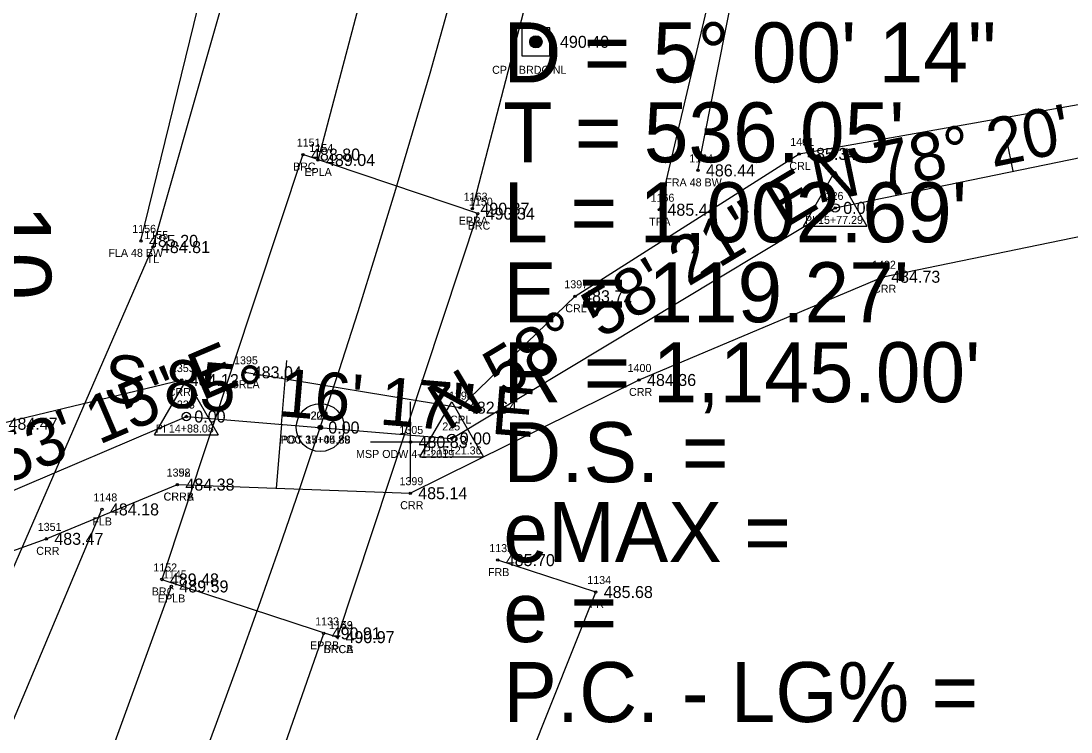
# Model space of a CAD drawing. Extents: x 1649047 to 1650429, y 896228 to 898747.
# Drawn here: x 1649848.7 to 1649979.9, y 897393.8 to 897482.7 of the extents above; entities that cross this region are included whole.
import ezdxf

# ---------------------------------------------------------------- set-up
doc = ezdxf.new("R2010")
doc.units = 0
for name, color, linetype in [('RD_EX_Bridge', 7, 'Continuous'), ('RD_EX_Bridge_txCode', 7, 'Continuous'), ('RD_EX_Fence_Other', 7, 'Continuous'), ('RD_EX_Fence_Other_txCode', 7, 'Continuous'), ('RD_EX_H2O', 7, 'Continuous'), ('RD_EX_H2O_txCode', 7, 'Continuous'), ('RD_EX_Road', 7, 'Continuous'), ('RD_EX_Road_txCode', 7, 'Continuous'), ('RD_EX_TX_Bridge_ELEV', 7, 'Continuous'), ('RD_EX_TX_Fence_Other_ELEV', 7, 'Continuous'), ('RD_EX_TX_H2O_ELEV', 7, 'Continuous'), ('RD_EX_TX_Misc_ELEV', 7, 'Continuous'), ('RD_EX_TX_Road_ELEV', 7, 'Continuous'), ('RD_EX_TX_VEG_ELEV', 7, 'Continuous'), ('RD_EX_VEG', 7, 'Continuous'), ('RD_EX_VEG_txCode', 7, 'Continuous'), ('RD_HC_Cl', 7, 'Continuous'), ('RD_HC_Data', 7, 'Continuous'), ('RD_HC_Data_Tic', 7, 'Continuous'), ('RD_HC_Survey', 7, 'Continuous'), ('RD_HC_Survey_ELEV', 7, 'Continuous'), ('RD_HC_Survey_txCode', 7, 'Continuous'), ('RD_HC_TX_Sta50', 7, 'Continuous'), ('RD_HC_txCode', 7, 'Continuous'), ('RD_SMD_Locator', 7, 'Continuous')]:
    doc.layers.add(name, color=color, linetype=linetype)

msp = doc.modelspace()

# ---------------------------------------------------------------- linework, layer by layer
at = {"layer": 'RD_EX_Bridge'}
msp.add_lwpolyline([(1649888.27, 897405.62), (1649905.8, 897458.58), (1649883.96, 897465.97), (1649866.32, 897412.83), (1649888.27, 897405.62)], dxfattribs=at)
at = {"layer": 'RD_EX_Fence_Other'}
for points in [[(1649933.32, 897463.99), (1649952.37, 897560.4), (1649962.02, 897611.35), (1649970.45, 897687.51), (1649972.87, 897702.51), (1649977.41, 897762.82), (1650017.96, 897774.28)], [(1649863.71, 897455.18), (1649880.54, 897523.95), (1649886.1, 897549.58), (1649888.54, 897562.35), (1649894.53, 897608.6), (1649889.75, 897641.9)], [(1649824.95, 897341.74), (1649840.87, 897378.89), (1649858.83, 897421.59)], [(1649933.62, 897283.21), (1649871.55, 897272.45), (1649870.07, 897285.06), (1649898.31, 897355.41), (1649920.55, 897411.26), (1649908.3, 897415.25)]]:
    msp.add_lwpolyline(points, dxfattribs=at)
at = {"layer": 'RD_EX_H2O'}
for p, q in [((1649897.4, 897425.03), (1649897.4, 897435.03)), ((1649892.4, 897430.03), (1649902.4, 897430.03))]:
    msp.add_line(p, q, dxfattribs=at)
for points in [[(1649876.68, 897438.74), (1649903.57, 897434.32), (1649917.97, 897448.25), (1649945.97, 897466.05), (1649997.07, 897475.13), (1650065.61, 897493.38), (1650098.97, 897502.84), (1650134.01, 897525.34), (1650184.58, 897534.43), (1650198.48, 897522.14), (1650246.85, 897542.98), (1650292.7, 897543.66), (1650345.21, 897558.55), (1650381.85, 897579.1), (1650386.65, 897572.92), (1650418.93, 897577.14)], [(1649868.27, 897424.7), (1649897.36, 897423.62), (1649925.96, 897437.78), (1649956.47, 897450.69), (1650000.97, 897459.86), (1650068.15, 897479.89), (1650103.08, 897490.82), (1650137.62, 897510.46), (1650180.41, 897516.6), (1650196.59, 897509.69), (1650246.91, 897526.88), (1650295.53, 897529.67), (1650347.35, 897546.47), (1650373.21, 897562.26), (1650385.6, 897559.55), (1650420.39, 897565.14)], [(1649868.8, 897437.77), (1649846.16, 897432.3), (1649822.76, 897417.33), (1649816.54, 897408.15), (1649799.76, 897408.66), (1649785.38, 897398.06), (1649752.08, 897411.48), (1649746.25, 897411.21), (1649738.94, 897415.88), (1649733.55, 897423.08), (1649741.13, 897430.63), (1649738.72, 897452.07)], [(1649610.78, 897003.58), (1649606.65, 897007.8), (1649603.49, 897018.01), (1649613.66, 897065.71), (1649613.8, 897087.62), (1649648.77, 897123.4), (1649673.15, 897145.36), (1649677.84, 897170.04), (1649704.36, 897195), (1649732.98, 897211.32), (1649741.05, 897244.13), (1649760.18, 897240.39), (1649790.48, 897304.8), (1649814.66, 897340.98), (1649827.92, 897366.62), (1649835.63, 897392.05), (1649839.2, 897413.36), (1649851.88, 897417.91), (1649868.27, 897424.7)]]:
    msp.add_lwpolyline(points, dxfattribs=at)
msp.add_circle((1649897.4, 897430.03), 0.15, dxfattribs=at)
at = {"layer": 'RD_EX_Road'}
for points in [[(1649905.13, 897459.2), (1649918.81, 897511.88), (1649930.39, 897563.05), (1649939.7, 897612.37), (1649946.83, 897662.25), (1649952.14, 897712.87), (1649954.77, 897762.63), (1649955.64, 897791.88), (1649955.33, 897812.31), (1649952.46, 897859.75), (1649947.95, 897909.71), (1649941.78, 897959.51), (1649933.15, 898009.23), (1649924.03, 898060.85), (1649913.91, 898112.48), (1649904.76, 898159.93)], [(1649885.84, 897465.29), (1649899.42, 897516.76), (1649910.69, 897567.43), (1649919.68, 897616.11), (1649926.54, 897664.67), (1649931.97, 897714.33), (1649935.04, 897763.32), (1649935.22, 897813.54), (1649932.16, 897857.76), (1649927.73, 897907.79), (1649922.24, 897954.81), (1649913.41, 898005.06), (1649903.99, 898056.19), (1649899.68, 898079.2), (1649896.48, 898096.53), (1649894.5, 898108.47), (1649884.77, 898155.82)], [(1649459.38, 896805.71), (1649486.55, 896839.62), (1649513.65, 896873.34), (1649538.22, 896902.56), (1649549.43, 896916.62), (1649583.1, 896957.27), (1649614.8, 896995.02), (1649647.06, 897035.69), (1649677.62, 897074.51), (1649708.33, 897114.44), (1649735.5, 897151.61), (1649762.11, 897192.19), (1649788.21, 897235.29), (1649812.17, 897279.73), (1649834.32, 897326.54), (1649852.94, 897371.82), (1649867.51, 897411.96)], [(1649474.75, 896792.65), (1649502.78, 896827.35), (1649565.2, 896903.92), (1649598.28, 896943.71), (1649629.8, 896982.26), (1649667.92, 897029.33), (1649693.13, 897061.44), (1649723.58, 897101.84), (1649752.37, 897141.09), (1649779.72, 897182.3), (1649806.12, 897225.84), (1649830.13, 897270.79), (1649852.39, 897317.43), (1649871.98, 897364.35), (1649886.55, 897406.09)]]:
    msp.add_lwpolyline(points, dxfattribs=at)
at = {"layer": 'RD_EX_VEG'}
for points in [[(1649617.18, 897070.52), (1649712.19, 897191.88), (1649745.96, 897241.38), (1649814.66, 897340.98), (1649833.89, 897382.46), (1649865.2, 897454.4), (1649884.45, 897522.02), (1649904.5, 897665.19), (1649923.9, 897762.32), (1649882.75, 898072.18)], [(1649928.51, 897459.07), (1649952.37, 897560.4), (1649962.02, 897611.35), (1649970.45, 897687.51), (1649977.41, 897762.82)]]:
    msp.add_lwpolyline(points, dxfattribs=at)
at = {"layer": 'RD_HC_Cl'}
for p, q in [((1649950.48, 897459.3), (1650001.12, 897469.74)), ((1649902.55, 897430.47), (1649950.48, 897459.3)), ((1649835.25, 897418.65), (1649869.38, 897433.21)), ((1649869.38, 897433.21), (1649902.55, 897430.47))]:
    msp.add_line(p, q, dxfattribs=at)
msp.add_arc((1648799.37, 897792.37), 1145, 320.82481, 10.99954, dxfattribs=at)
at = {"layer": 'RD_HC_Data'}
for p, q in [((1649946.51, 897457.01), (1649950.48, 897463.88)), ((1649950.48, 897463.88), (1649954.45, 897457.01)), ((1649946.51, 897457.01), (1649954.45, 897457.01)), ((1649865.41, 897430.92), (1649869.38, 897437.8)), ((1649869.38, 897437.8), (1649873.35, 897430.92)), ((1649898.58, 897428.18), (1649902.55, 897435.06)), ((1649902.55, 897435.06), (1649906.52, 897428.18)), ((1649865.41, 897430.92), (1649873.35, 897430.92)), ((1649898.58, 897428.18), (1649906.52, 897428.18))]:
    msp.add_line(p, q, dxfattribs=at)
for centre, radius in [((1649950.48, 897459.3), 0.529), ((1649886.12, 897431.83), 3), ((1649886.12, 897431.83), 3), ((1649869.38, 897433.21), 0.529), ((1649886.12, 897431.83), 0.282), ((1649886.12, 897431.83), 0.282), ((1649902.55, 897430.47), 0.529)]:
    msp.add_circle(centre, radius, dxfattribs=at)
at = {"layer": 'RD_HC_Data_Tic'}
for p, q in [((1649972.72, 897463.89), (1649971.91, 897467.8)), ((1649881.26, 897432.23), (1649881.92, 897440.2)), ((1649881.26, 897432.23), (1649880.6, 897424.26))]:
    msp.add_line(p, q, dxfattribs=at)
at = {"layer": 'RD_HC_Survey'}
for p, q in [((1649912.33, 897479.89), (1649912.33, 897480.25)), ((1649912.35, 897479.81), (1649912.35, 897480.33)), ((1649912.38, 897479.75), (1649912.38, 897480.39)), ((1649912.4, 897479.7), (1649912.4, 897480.44)), ((1649912.43, 897479.66), (1649912.43, 897480.48)), ((1649912.45, 897479.62), (1649912.45, 897480.52)), ((1649912.48, 897479.59), (1649912.48, 897480.55)), ((1649912.5, 897479.56), (1649912.5, 897480.58)), ((1649912.53, 897479.53), (1649912.53, 897480.61)), ((1649912.55, 897479.51), (1649912.55, 897480.63)), ((1649912.57, 897479.49), (1649912.57, 897480.66)), ((1649912.6, 897479.47), (1649912.6, 897480.68)), ((1649912.62, 897479.45), (1649912.62, 897480.69)), ((1649912.65, 897479.43), (1649912.65, 897480.71)), ((1649912.67, 897479.41), (1649912.67, 897480.73)), ((1649912.7, 897479.4), (1649912.7, 897480.74)), ((1649912.72, 897479.39), (1649912.72, 897480.75)), ((1649912.75, 897479.37), (1649912.75, 897480.77)), ((1649912.77, 897479.36), (1649912.77, 897480.78)), ((1649912.8, 897479.35), (1649912.8, 897480.79)), ((1649912.82, 897479.34), (1649912.82, 897480.8)), ((1649912.85, 897479.34), (1649912.85, 897480.81)), ((1649912.87, 897479.33), (1649912.87, 897480.81)), ((1649912.9, 897479.32), (1649912.9, 897480.82)), ((1649912.92, 897479.32), (1649912.92, 897480.82)), ((1649912.95, 897479.31), (1649912.95, 897480.83)), ((1649912.97, 897479.31), (1649912.97, 897480.83)), ((1649913, 897479.31), (1649913, 897480.84)), ((1649913.02, 897479.3), (1649913.02, 897480.84)), ((1649913.04, 897479.3), (1649913.04, 897480.84)), ((1649913.07, 897479.3), (1649913.07, 897480.84)), ((1649913.09, 897479.3), (1649913.09, 897480.84)), ((1649913.12, 897479.3), (1649913.12, 897480.84)), ((1649913.14, 897479.3), (1649913.14, 897480.84)), ((1649913.17, 897479.31), (1649913.17, 897480.83)), ((1649913.19, 897479.31), (1649913.19, 897480.83)), ((1649913.22, 897479.31), (1649913.22, 897480.83)), ((1649913.24, 897479.32), (1649913.24, 897480.82)), ((1649913.27, 897479.33), (1649913.27, 897480.82)), ((1649913.29, 897479.33), (1649913.29, 897480.81)), ((1649913.32, 897479.34), (1649913.32, 897480.8)), ((1649913.34, 897479.35), (1649913.34, 897480.79)), ((1649913.37, 897479.36), (1649913.37, 897480.78)), ((1649913.39, 897479.37), (1649913.39, 897480.77)), ((1649913.42, 897479.38), (1649913.42, 897480.76)), ((1649913.44, 897479.39), (1649913.44, 897480.75)), ((1649913.47, 897479.41), (1649913.47, 897480.73)), ((1649913.49, 897479.42), (1649913.49, 897480.72)), ((1649913.52, 897479.44), (1649913.52, 897480.7)), ((1649913.54, 897479.46), (1649913.54, 897480.68)), ((1649913.56, 897479.48), (1649913.56, 897480.66)), ((1649913.59, 897479.5), (1649913.59, 897480.64)), ((1649913.61, 897479.52), (1649913.61, 897480.62)), ((1649913.64, 897479.55), (1649913.64, 897480.6)), ((1649913.66, 897479.57), (1649913.66, 897480.57)), ((1649913.69, 897479.61), (1649913.69, 897480.54)), ((1649913.71, 897479.64), (1649913.71, 897480.5)), ((1649913.74, 897479.68), (1649913.74, 897480.46)), ((1649913.76, 897479.72), (1649913.76, 897480.42)), ((1649913.79, 897479.78), (1649913.79, 897480.36)), ((1649913.81, 897479.85), (1649913.81, 897480.29)), ((1649913.84, 897479.96), (1649913.84, 897480.18))]:
    msp.add_line(p, q, dxfattribs=at)
msp.add_lwpolyline([(1649914.83, 897481.82), (1649911.33, 897481.82), (1649911.33, 897478.32), (1649914.83, 897478.32)], close=True, dxfattribs=at)
msp.add_circle((1649913.08, 897480.07), 0.769, dxfattribs=at)
at = {"layer": 'RD_SMD_Locator'}
for centre in [(1649913.08, 897480.07), (1649883.96, 897465.97), (1649885.84, 897465.29), (1649945.97, 897466.05), (1649933.32, 897463.99), (1649905.13, 897459.2), (1649928.51, 897459.07), (1649950.48, 897459.3), (1649905.8, 897458.58), (1649863.71, 897455.18), (1649865.2, 897454.4), (1649956.47, 897450.69), (1649917.97, 897448.25), (1649868.8, 897437.77), (1649876.68, 897438.74), (1649925.96, 897437.78), (1649903.57, 897434.32), (1649869.38, 897433.21), (1649886.12, 897431.83), (1649886.12, 897431.83), (1649902.55, 897430.47), (1649868.27, 897424.7), (1649868.27, 897424.7), (1649897.36, 897423.62), (1649858.83, 897421.59), (1649851.88, 897417.91), (1649908.3, 897415.25), (1649866.32, 897412.83), (1649867.51, 897411.96), (1649920.55, 897411.26), (1649886.55, 897406.09), (1649888.27, 897405.62), (1649888.27, 897405.62)]:
    msp.add_circle(centre, 0.15, dxfattribs=at)

# ---------------------------------------------------------------- texts
at = {"layer": 'RD_EX_Bridge_txCode'}
for s, p in [('1151', (1649883.18, 897466.97)), ('BRC', (1649882.71, 897463.97)), ('1150', (1649904.7, 897459.58)), ('BRC', (1649904.55, 897456.58)), ('1152', (1649865.25, 897413.83)), ('BRC', (1649865.06, 897410.83)), ('1149', (1649887.21, 897406.62)), ('1153', (1649887.21, 897406.62)), ('BRCA', (1649886.53, 897403.62)), ('BRCB', (1649886.55, 897403.62))]:
    msp.add_text(s, height=1, dxfattribs=at).set_placement(p)
at = {"layer": 'RD_EX_Fence_Other_txCode'}
for s, p in [('1164', (1649932.24, 897464.99)), ('FRA 48 BW', (1649929.24, 897461.99)), ('1156', (1649862.62, 897456.18)), ('FLA 48 BW', (1649859.64, 897453.18)), ('1148', (1649857.77, 897422.59)), ('FLB', (1649857.63, 897419.59)), ('1135', (1649907.24, 897416.25)), ('FRB', (1649907.08, 897413.25)), ('1134', (1649919.49, 897412.26)), ('FR', (1649919.8, 897409.26))]:
    msp.add_text(s, height=1, dxfattribs=at).set_placement(p)
at = {"layer": 'RD_EX_H2O_txCode'}
for s, p in [('1401', (1649944.86, 897467.05)), ('CRL', (1649944.74, 897464.05)), ('1402', (1649955.08, 897451.69)), ('1397', (1649916.62, 897449.25)), ('CRR', (1649955.21, 897448.69)), ('CRL', (1649916.74, 897446.25)), ('1395', (1649875.34, 897439.74)), ('1353', (1649867.45, 897438.77)), ('1400', (1649924.53, 897438.78)), ('CRRA', (1649867.06, 897435.77)), ('CRLA', (1649874.97, 897436.74)), ('CRR', (1649924.71, 897435.78)), ('1396', (1649902.2, 897435.32)), ('CRL', (1649902.34, 897432.32)), ('1305', (1649896.01, 897431.03)), ('MSP ODW 4-1-2019', (1649890.59, 897428.03)), ('1352', (1649866.92, 897425.7)), ('1398', (1649866.92, 897425.7)), ('1399', (1649896.02, 897424.62)), ('CRRA', (1649866.53, 897422.7)), ('CRRB', (1649866.54, 897422.7)), ('CRR', (1649896.11, 897421.62)), ('1351', (1649850.81, 897418.91)), ('CRR', (1649850.62, 897415.91))]:
    msp.add_text(s, height=1, dxfattribs=at).set_placement(p)
at = {"layer": 'RD_EX_Road_txCode'}
for s, p in [('1154', (1649884.77, 897466.29)), ('EPLA', (1649884.14, 897463.29)), ('1163', (1649904.05, 897460.2)), ('EPRA', (1649903.42, 897457.2)), ('1145', (1649866.45, 897412.96)), ('EPLB', (1649865.83, 897409.96)), ('1133', (1649885.48, 897407.09)), ('EPRB', (1649884.84, 897404.09))]:
    msp.add_text(s, height=1, dxfattribs=at).set_placement(p)
at = {"layer": 'RD_EX_TX_Bridge_ELEV'}
for s, p in [('488.80', (1649884.96, 897465.22)), ('490.34', (1649906.8, 897457.83)), ('489.48', (1649867.32, 897412.08)), ('490.97', (1649889.27, 897404.87)), ('490.97', (1649889.27, 897404.87))]:
    msp.add_text(s, height=1.5, dxfattribs=at).set_placement(p)
at = {"layer": 'RD_EX_TX_Fence_Other_ELEV'}
for s, p in [('486.44', (1649934.32, 897463.24)), ('485.20', (1649864.71, 897454.43)), ('484.18', (1649859.83, 897420.84)), ('485.70', (1649909.3, 897414.5)), ('485.68', (1649921.55, 897410.51))]:
    msp.add_text(s, height=1.5, dxfattribs=at).set_placement(p)
at = {"layer": 'RD_EX_TX_H2O_ELEV'}
for s, p in [('485.34', (1649946.97, 897465.3)), ('484.73', (1649957.47, 897449.94)), ('483.72', (1649918.97, 897447.5)), ('483.04', (1649877.68, 897437.99)), ('484.12', (1649869.8, 897437.02)), ('484.36', (1649926.96, 897437.03)), ('482.64', (1649904.57, 897433.57)), ('484.47', (1649847.16, 897431.55)), ('484.38', (1649869.27, 897423.95)), ('484.38', (1649869.27, 897423.95)), ('485.14', (1649898.36, 897422.87)), ('483.47', (1649852.88, 897417.16))]:
    msp.add_text(s, height=1.5, dxfattribs=at).set_placement(p)
at = {"layer": 'RD_EX_TX_Misc_ELEV'}
msp.add_text('480.83', height=1.5, dxfattribs=at).set_placement((1649898.4, 897429.28))
at = {"layer": 'RD_EX_TX_Road_ELEV'}
for s, p in [('489.04', (1649886.84, 897464.54)), ('490.37', (1649906.13, 897458.45)), ('489.59', (1649868.51, 897411.21)), ('490.91', (1649887.55, 897405.34))]:
    msp.add_text(s, height=1.5, dxfattribs=at).set_placement(p)
at = {"layer": 'RD_EX_TX_VEG_ELEV'}
for s, p in [('485.44', (1649929.51, 897458.32)), ('484.81', (1649866.2, 897453.65))]:
    msp.add_text(s, height=1.5, dxfattribs=at).set_placement(p)
at = {"layer": 'RD_EX_VEG_txCode'}
for s, p in [('1166', (1649927.4, 897460.07)), ('TRA', (1649927.22, 897457.07)), ('1155', (1649864.14, 897455.4)), ('TL', (1649864.43, 897452.4))]:
    msp.add_text(s, height=1, dxfattribs=at).set_placement(p)
at = {"layer": 'RD_HC_Data'}
for s, p in [('D = 5%%d 00\' 14"', (1649909, 897475)), ("T = 536.05'", (1649909, 897465)), ("L = 1,002.69'", (1649909, 897455)), ("E = 119.27'", (1649909, 897445)), ("R = 1,145.00'", (1649909, 897435)), ('D.S. = ', (1649909, 897425)), ('eMAX = ', (1649909, 897415)), ('e = ', (1649909, 897405)), ('P.C. - LG% = ', (1649909, 897395))]:
    msp.add_text(s, height=7.5, dxfattribs=at).set_placement(p)
for s, rotation, p in [('N 78%%d 20\' 39" E', 11.6559, (1649948.2, 897459.85)), ('N 58%%d 58\' 21" E', 31.0276, (1649902.03, 897431.32)), ('N 66%%d 53\' 15" E', 23.1125, (1649826.19, 897415.87)), ('S 85%%d 16\' 17" E', 355.2713, (1649858.9, 897435.08))]:
    msp.add_text(s, height=6, rotation=rotation, dxfattribs=at).set_placement(p)
at = {"layer": 'RD_HC_Survey_ELEV'}
for s, p in [('490.40', (1649916.08, 897479.32)), ('0.00', (1649951.48, 897458.55)), ('0.00', (1649870.38, 897432.46)), ('0.00', (1649887.12, 897431.08)), ('0.00', (1649887.12, 897431.08)), ('0.00', (1649903.55, 897429.72))]:
    msp.add_text(s, height=1.5, dxfattribs=at).set_placement(p)
at = {"layer": 'RD_HC_Survey_txCode'}
msp.add_text('CP 6 BRDG NL', height=1, dxfattribs=at).set_placement((1649907.6, 897476.07))
at = {"layer": 'RD_HC_TX_Sta50'}
msp.add_text('10', height=8, rotation=270.2161, dxfattribs=at).set_placement((1649844.46, 897459.66))
at = {"layer": 'RD_HC_txCode'}
for s, p in [('226', (1649949.28, 897460.3)), ('PI 15+77.29', (1649946.7, 897457.3)), ('223', (1649868.2, 897434.21)), ('203', (1649884.9, 897432.83)), ('224', (1649884.94, 897432.83)), ('PI 14+88.08', (1649865.56, 897431.21)), ('225', (1649901.37, 897431.47)), ('POC 37+45.89', (1649880.96, 897429.83)), ('POT 15+04.88', (1649881.17, 897429.83)), ('PI 15+21.36', (1649899.03, 897428.47))]:
    msp.add_text(s, height=1, dxfattribs=at).set_placement(p)

doc.saveas('drawing.dxf')
